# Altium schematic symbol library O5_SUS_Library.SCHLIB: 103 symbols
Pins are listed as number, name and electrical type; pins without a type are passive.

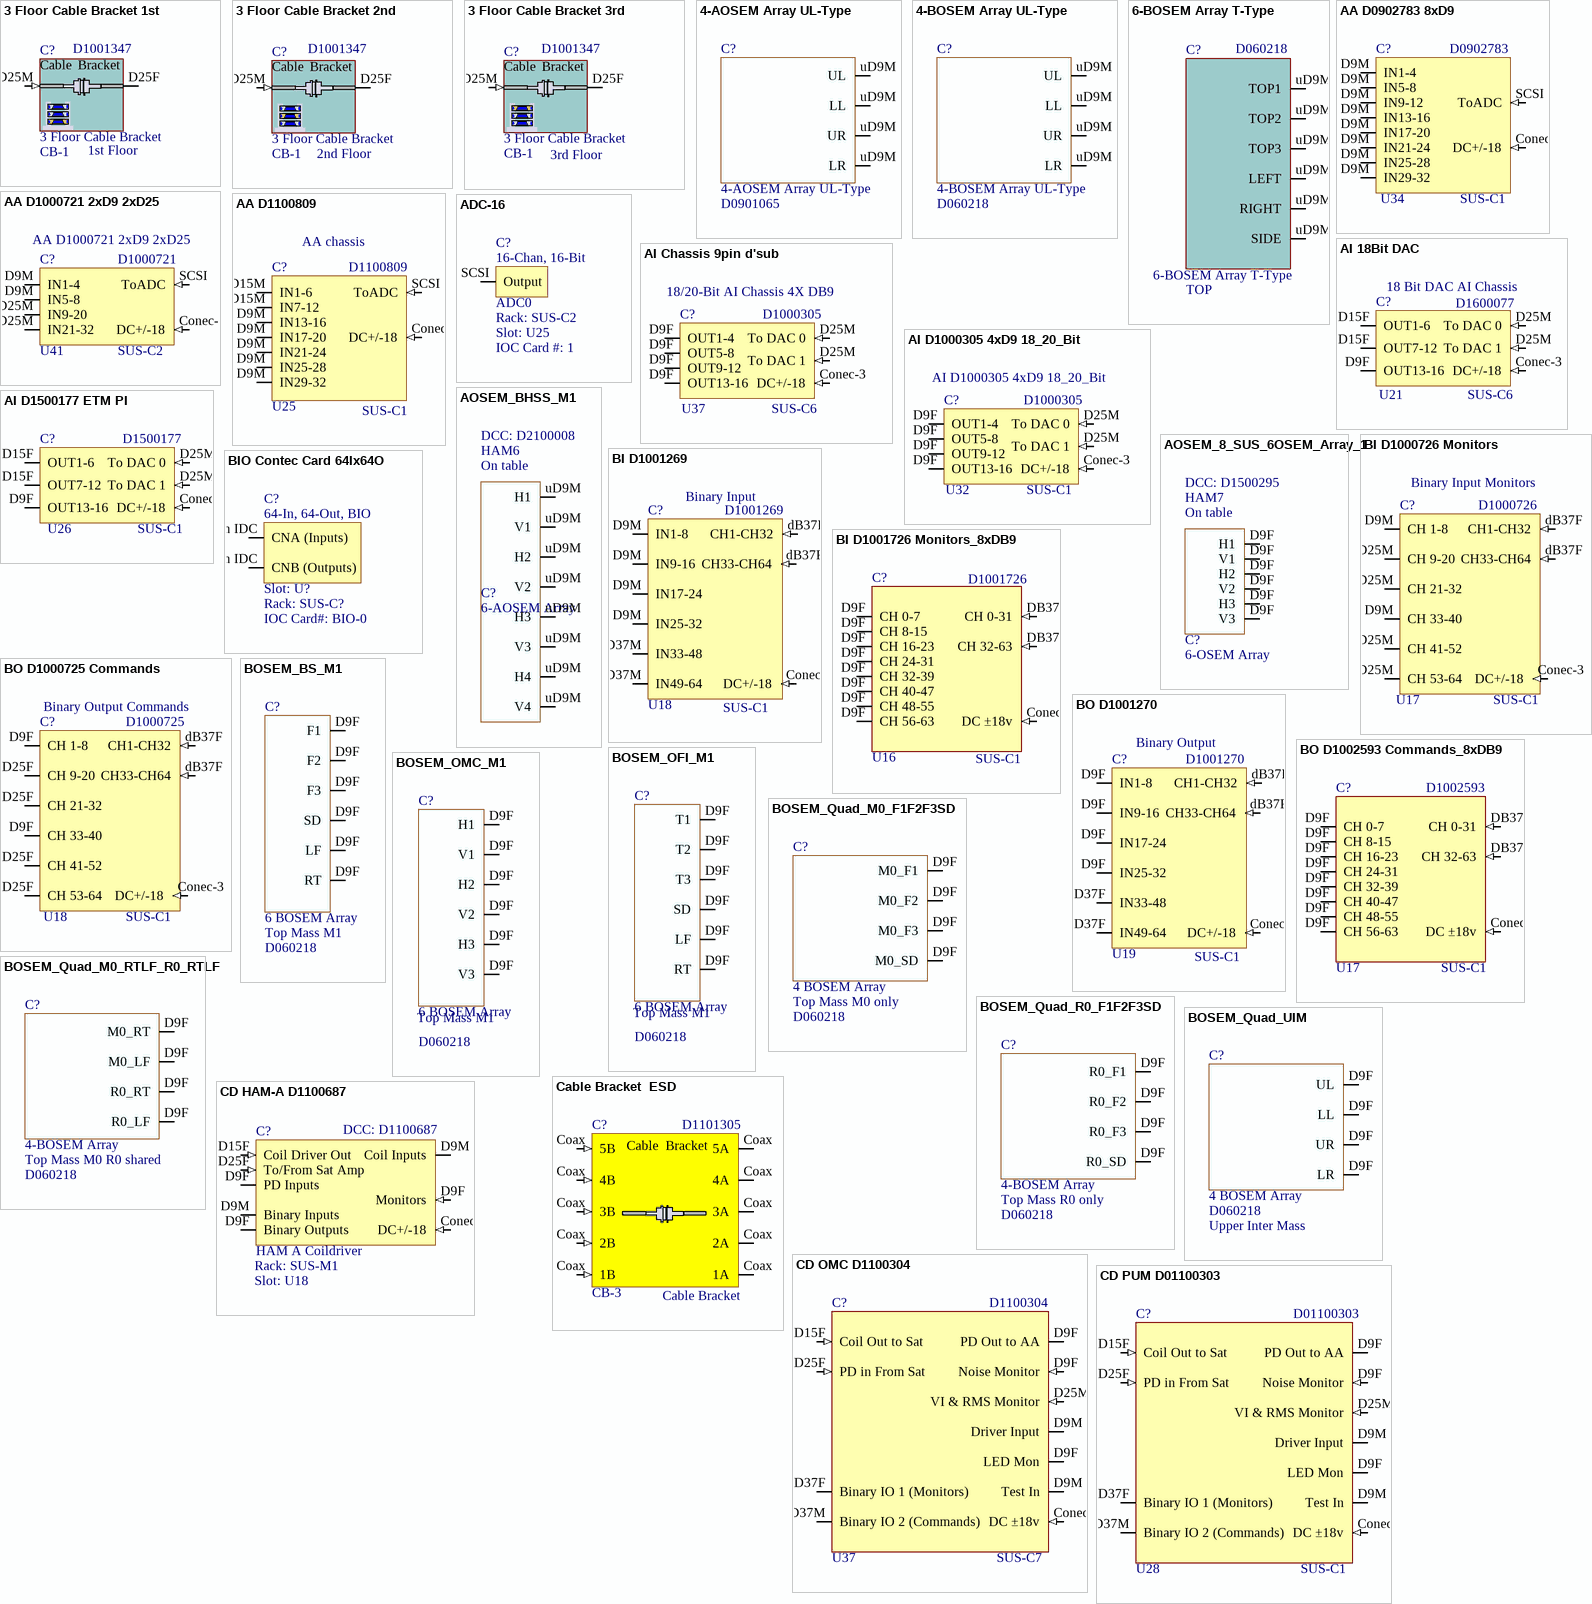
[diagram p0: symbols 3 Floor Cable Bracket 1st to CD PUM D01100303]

## 3 Floor Cable Bracket 1st
designator C?, comment 3 Floor Cable Bracket  Rack: CB-1  Slot: 1st Floor  DCC: D1001347
Cable Bracket; Serial: Sxxxxxxx; System: SUS
pins: D25F, D25M (in)

## 3 Floor Cable Bracket 2nd
designator C?, comment 3 Floor Cable Bracket  Rack: CB-1  DCC: D1001347  Slot: 2nd Floor
Cable Bracket; Serial: Sxxxxxxx; System: SUS
pins: D25F, D25M (in)

## 3 Floor Cable Bracket 3rd
designator C?, comment 3 Floor Cable Bracket  Rack: CB-1  DCC: D1001347  Slot: 3rd Floor
Cable Bracket; Serial: Sxxxxxxx; System: SUS
pins: D25F, D25M (in)

## 4-AOSEM Array UL-Type
designator C?  DCC: D0901065
Rack: R?; Slot: U?; Serial: Sxxxxxxx; System: SUS
pins: uD9M UL, uD9M LL, uD9M UR, uD9M LR

## 4-BOSEM Array UL-Type
designator C?  DCC: D060218
Rack: R?; Slot: U?; Serial: Sxxxxxxx; System: SUS
pins: uD9M UL, uD9M LL, uD9M UR, uD9M LR

## 6-BOSEM Array T-Type
designator C?  Parameter 1: TOP  DCC: D060218
Serial: Sxxxxxxx; System: SUS; Slot: U?; Rack: SUS-R?
pins: uD9M TOP1, uD9M TOP2, uD9M TOP3, uD9M LEFT, uD9M RIGHT, uD9M SIDE

## AA D0902783 8xD9
designator C?  DCC: D0902783  Rack: SUS-C1  Slot: U34  (hidden comment: AA D0902783 8xD9)
Serial: Sxxxxxxx; System: SUS
pins: Conec-3 DC+/-18 (in), D9M IN1-4, D9M IN5-8, D9M IN9-12, D9M IN13-16, D9M IN17-20, D9M IN21-24, D9M IN25-28, D9M IN29-32, SCSI ToADC (in)

## AA D1000721 2xD9 2xD25
designator C?  Slot: U41  Rack: SUS-C2  DCC: D1000721
Serial: Sxxxxxxx; System: SUS; Parameter: AA chassis
pins: Conec-3 DC+/-18 (in), D9M IN1-4, D9M IN5-8, D25M IN9-20, D25M IN21-32, SCSI ToADC (in)

## AA D1100809
designator C?, comment Slot: U25  Rack: SUS-C1  DCC: D1100809  (hidden comment: AA Chassis)
Serial: Sxxxxxxx; System: SUS
pins: Conec-3 DC+/-18 (in), D9M IN13-16, D9M IN17-20, D9M IN21-24, D9M IN25-28, D9M IN29-32, D15M IN1-6, D15M IN7-12, SCSI ToADC (in)

## ADC-16
designator C?, comment ADC0  Rack: SUS-C2  Slot: U25  IOC Card #: 1
16 Chan, 16 Bit ADC
pins: SCSI Output

## AI 18Bit DAC
designator C?, comment Rack: SUS-C6  Slot: U21  DCC: D1600077  Parameter: 18 Bit DAC AI Chassis  (hidden comment: AI chassis 18Bit)
Serial: Sxxxxxxx; System: SUS
pins: Conec-3 DC+/-18 (in), D9F OUT13-16, D15F OUT1-6, D15F OUT7-12, D25M To DAC 0 (in), D25M To DAC 1 (in)

## AI Chassis 9pin d'sub
designator C?  value 18/20-Bit AI Chassis 4X DB9  Rack: SUS-C6  Slot: U37  DCC: D1000305  (hidden comment: AI Chassis 9pin d'sub)
System: SUS; Serial: Sxxxxxxx
pins: Conec-3 DC+/-18 (in) "pin 7", D9F OUT1-4 "pin 1", D9F OUT5-8 "pin 2", D9F OUT9-12 "pin 3", D9F OUT13-16 "pin 4", D25M To DAC 0 (in) "pin 5", D25M To DAC 1 (in) "pin 6"

## AI D1000305 4xD9 18_20_Bit
designator C?  Rack: SUS-C1  Slot: U32  DCC: D1000305
System: SUS; Serial: Sxxxxxxx
pins: Conec-3 DC+/-18 (in), D9F OUT1-4, D9F OUT5-8, D9F OUT9-12, D9F OUT13-16, D25M To DAC 0 (in), D25M To DAC 1 (in)

## AI D1500177 ETM PI
designator C?, comment Rack: SUS-C1  Slot: U26  DCC: D1500177  (hidden comment: AI chassis 18Bit)
Serial: Sxxxxxxx; System: SUS; Parameter: 18 Bit DAC AI Chassis
pins: Conec-3 DC+/-18 (in), D9F OUT13-16, D15F OUT1-6, D15F OUT7-12, D25M To DAC 0 (in), D25M To DAC 1 (in)

## AOSEM_8_SUS_6OSEM_Array_1
designator C?, comment 6-OSEM Array  DCC: D1500295  Rack: HAM7  Slot: On table
OPO Suspended Platform OSEM Array
pins: D9F H1, D9F H2, D9F V1, D9F H3, D9F V2, D9F V3

## AOSEM_BHSS_M1
designator C?, comment 6-AOSEM Array  DCC: D2100008  Rack: HAM6  Slot: On table
BHSS Suspended Platform AOSEM Array
pins: uD9M H1, uD9M H2, uD9M V1, uD9M H3, uD9M V2, uD9M V3, uD9M H4, uD9M V4

## BI D1000726 Monitors
designator C?  Parameter: Binary Input Monitors  Slot: U17  Rack: SUS-C1  DCC: D1000726  (hidden comment: BI D1000726 Monitors)
Serial: Sxxxxxxx; System: SUS
pins: Conec-3 DC+/-18 (in), D9M CH 1-8, D9M CH 33-40, D25M CH 9-20, D25M CH 21-32, D25M CH 41-52, D25M CH 53-64, dB37F CH1-CH32 (in), dB37F CH33-CH64 (in)

## BI D1001269
designator C?, comment Slot: U18  Rack: SUS-C1  Parameter: Binary Input  DCC: D1001269  (hidden comment: Binary Input Interface)
Serial: Sxxxxxxx; System: SUS
pins: Conec-3 DC+/-18 (in), D9M IN1-8, D9M IN9-16, D9M IN17-24, D9M IN25-32, D37M IN33-48, D37M IN49-64, dB37F CH1-CH32 (in), dB37F CH33-CH64 (in)

## BI D1001726 Monitors_8xDB9
designator C?  Slot: U16  Rack: SUS-C1  DCC: D1001726  (hidden comment: BI D1001726 Monitors_8xDB9)
Serial: Sxxxxxxx; System: SUS
pins: Conec 3 DC ±18v (in), D9F CH 0-7, D9F CH 8-15, D9F CH 16-23, D9F CH 24-31, D9F CH 32-39, D9F CH 40-47, D9F CH 48-55, D9F CH 56-63, DB37F CH 0-31 (in), DB37F CH 32-63 (in)

## BIO Contec Card 64Ix64O
designator C?  Slot: U?  Rack: SUS-C?  IOC Card#: BIO-0  (hidden comment: BIO Contec Card 64Ix64O)
System: SUS
pins: 100Pin IDC CNA (Inputs), 100Pin IDC CNB (Outputs)

## BO D1000725 Commands
designator C?  Parameter: Binary Output Commands  Slot: U18  Rack: SUS-C1  DCC: D1000725  (hidden comment: BO D1000725 Commands)
Serial: Sxxxxxxx; System: SUS
pins: Conec-3 DC+/-18 (in), D9F CH 1-8, D9F CH 33-40, D25F CH 9-20, D25F CH 21-32, D25F CH 41-52, D25F CH 53-64, dB37F CH1-CH32 (in), dB37F CH33-CH64 (in)

## BO D1001270
designator C?, comment Slot: U19  Rack: SUS-C1  Parameter: Binary Output  DCC: D1001270  (hidden comment: Binary Output Interface)
Serial: Sxxxxxxx; System: SUS
pins: Conec-3 DC+/-18 (in), D9F IN1-8, D9F IN9-16, D9F IN17-24, D9F IN25-32, D37F IN33-48, D37F IN49-64, dB37F CH1-CH32 (in), dB37F CH33-CH64 (in)

## BO D1002593 Commands_8xDB9
designator C?  Slot: U17  Rack: SUS-C1  DCC: D1002593  (hidden comment: BO D1002593 Commands_8xDB9)
Serial: Sxxxxxxx; System: SUS
pins: Conec 3 DC ±18v (in), D9F CH 0-7, D9F CH 8-15, D9F CH 16-23, D9F CH 24-31, D9F CH 32-39, D9F CH 40-47, D9F CH 48-55, D9F CH 56-63, DB37F CH 0-31 (in), DB37F CH 32-63 (in)

## BOSEM_BS_M1
designator C?, comment 6 BOSEM Array  Parameter: Top Mass M1  DCC: D060218
BOSEM; Serial: Sxxxxxxx; System: SUS; Rack: R?; Slot: U?
pins: D9F F1, D9F F2, D9F F3, D9F SD, D9F LF, D9F RT

## BOSEM_OFI_M1
designator C?, comment 6 BOSEM Array  Parameter: Top Mass M1  DCC: D060218
BOSEM; Serial: Sxxxxxxx; System: SUS; Rack: R?; Slot: U?
pins: D9F T1, D9F T2, D9F T3, D9F SD, D9F LF, D9F RT

## BOSEM_OMC_M1
designator C?, comment 6 BOSEM Array  Parameter: Top Mass M1  DCC: D060218
BOSEM; Serial: Sxxxxxxx; System: SUS; Rack: R?; Slot: U?
pins: D9F H1, D9F V1, D9F H2, D9F V2, D9F H3, D9F V3

## BOSEM_Quad_M0_F1F2F3SD
designator C?, comment 4 BOSEM Array  Parameter: Top Mass M0 only  DCC: D060218
BOSEM; Serial: Sxxxxxxx; System: SUS; Rack: R?; Slot: U?
pins: D9F M0_F1, D9F M0_F2, D9F M0_F3, D9F M0_SD

## BOSEM_Quad_M0_RTLF_R0_RTLF
designator C?, comment 4-BOSEM Array  Parameter: Top Mass M0 R0 shared  DCC: D060218
BOSEM; Rack: R?; Slot: U?; Serial: Sxxxxxxx; System: SUS
pins: D9F M0_RT, D9F M0_LF, D9F R0_RT, D9F R0_LF

## BOSEM_Quad_R0_F1F2F3SD
designator C?, comment 4-BOSEM Array  Parameter: Top Mass R0 only  DCC: D060218
BOSEM; System: SUS; Slot: U?; Serial: Sxxxxxxx; Rack: R?
pins: D9F R0_F2, D9F R0_F1, D9F R0_SD, D9F R0_F3

## BOSEM_Quad_UIM
designator C?, comment 4 BOSEM Array  DCC: D060218  Parameter: Upper Inter Mass
BOSEM; Rack: R?; Serial: Sxxxxxxx; Slot: U?; System: SUS
pins: D9F UL, D9F LL, D9F UR, D9F LR

## Cable Bracket  ESD
designator C?, comment Slot: CB-3  DCC: D1101305  (hidden comment: Cable Bracket)
Rack: SUS-R?; Serial: Sxxxxxxx; System: SUS
pins: Coax 5B (in), Coax 5A, Coax 4A, Coax 3A, Coax 2A, Coax 1A, Coax 4B (in), Coax 3B (in), Coax 2B (in), Coax 1B (in)

## CD HAM-A D1100687
designator C?, comment HAM A Coildriver  DCC: D1100687  Rack: SUS-M1  Slot: U18
Serial: Sxxxxxxx; System: ISC
pins: Conec-3 DC+/-18 (in), D9F PD Inputs, D9F Monitors (in), D9F Binary Outputs, D9M Coil Inputs, D9M Binary Inputs, D15F Coil Driver Out (in), D25F To/From Sat Amp (in)

## CD OMC D1100304
designator C?, comment Slot: U37  Rack: SUS-C7  DCC: D1100304  (hidden comment: CD OMC TCD D1100304)
System: SUS; Serial: Sxxxxxxx
pins: Conec 3 DC ±18v (in), D9F PD Out to AA, D9F LED Mon, D9F Noise Monitor (in), D9M Test In, D9M Driver Input, D15F Coil Out to Sat (in), D25F PD in From Sat (in), D25M VI & RMS Monitor (in), D37F Binary IO 1 (Monitors), D37M Binary IO 2 (Commands)

## CD PUM D01100303
designator C?  Slot: U28  Rack: SUS-C1  DCC: D01100303  (hidden comment: CD PUM D01100303)
System: SUS; Serial: Sxxxxxxx
pins: Conec 3 DC ±18v (in), D9F PD Out to AA, D9F LED Mon, D9F Noise Monitor (in), D9M Test In, D9M Driver Input, D15F Coil Out to Sat (in), D25F PD in From Sat (in), D25M VI & RMS Monitor (in), D37F Binary IO 1 (Monitors), D37M Binary IO 2 (Commands)

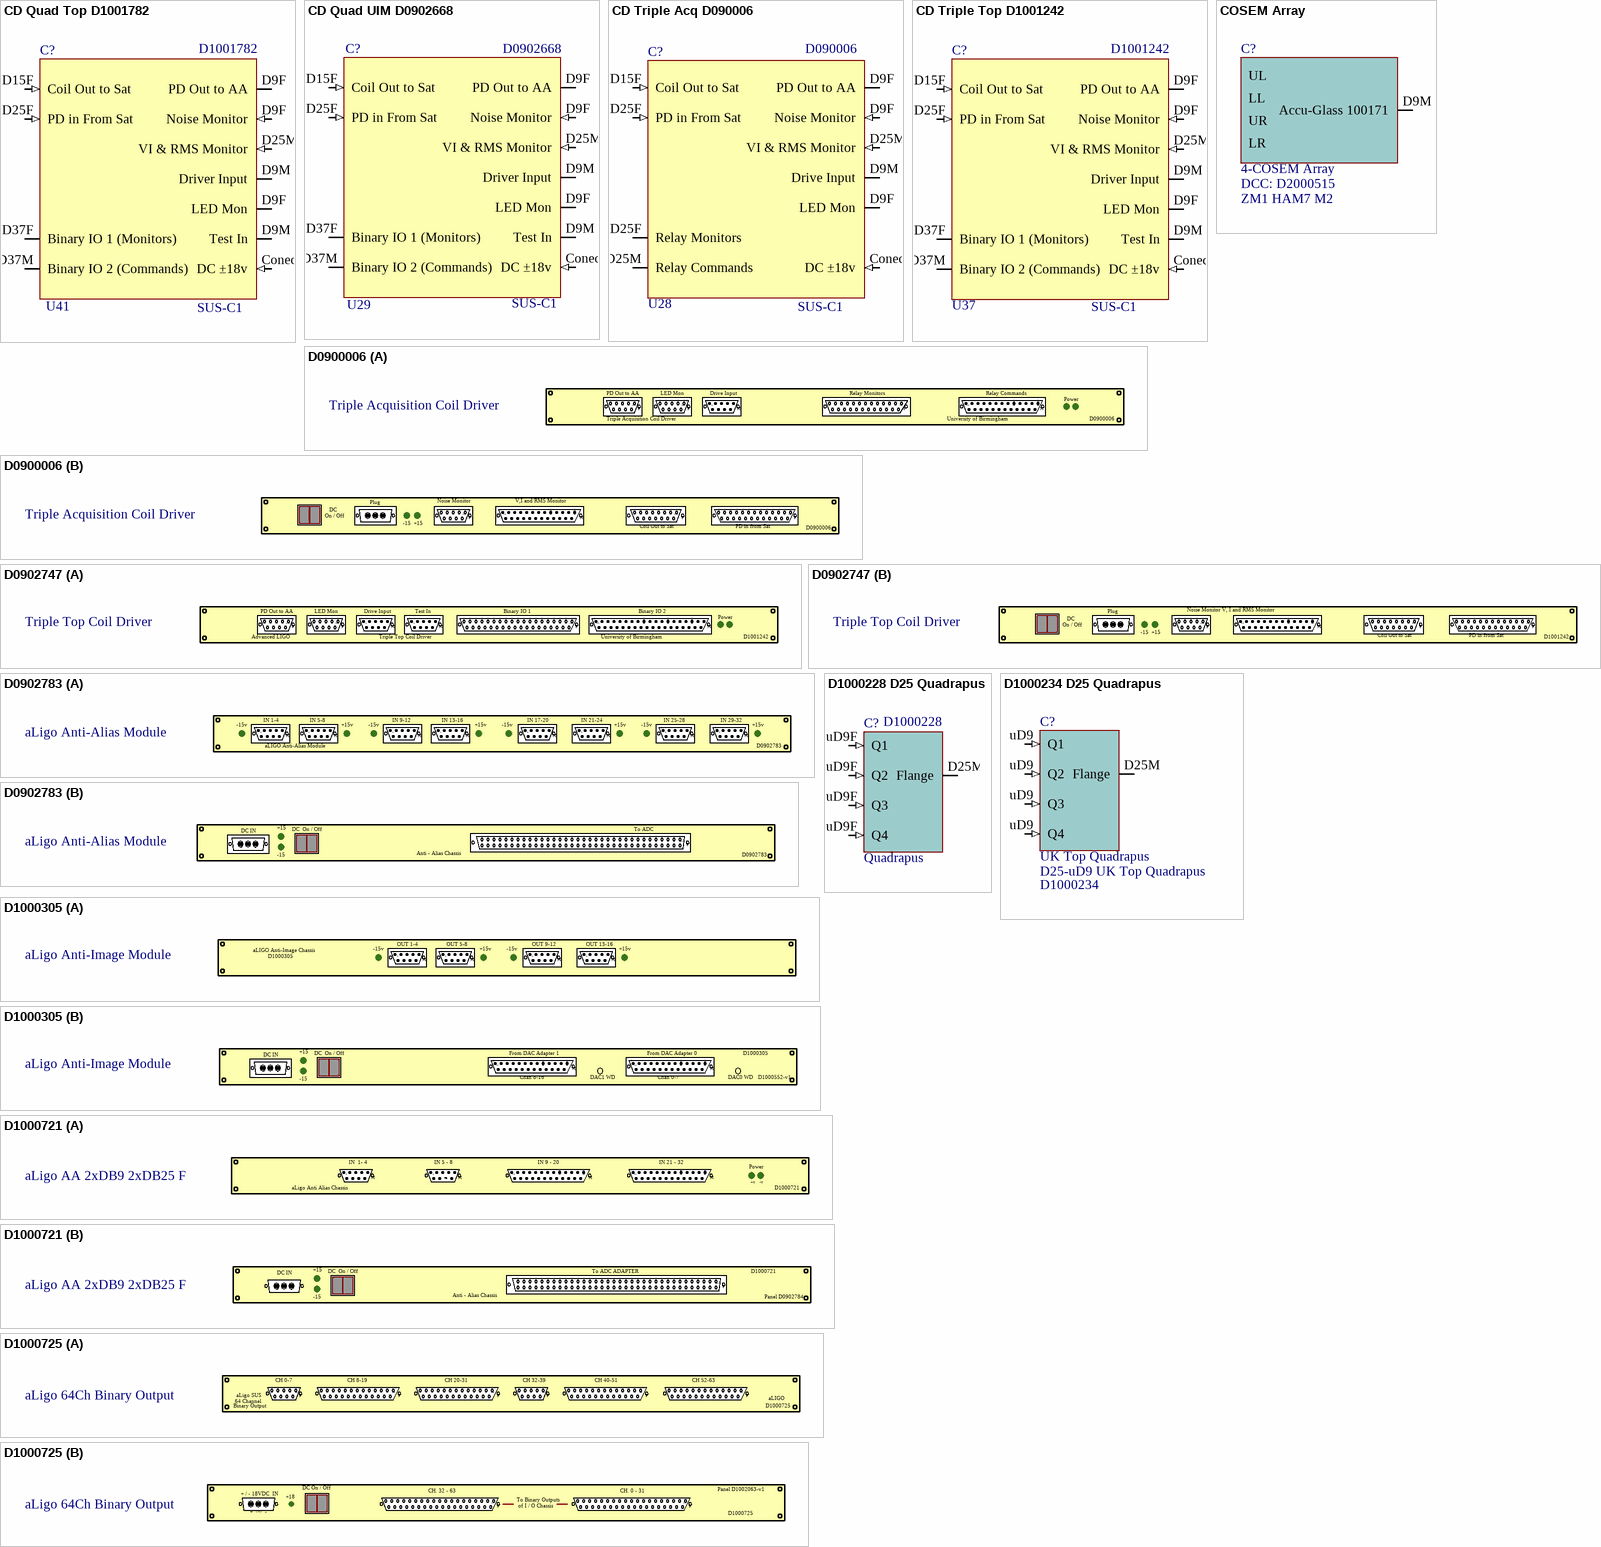
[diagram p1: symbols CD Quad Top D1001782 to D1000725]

## CD Quad Top D1001782
designator C?  Rack: SUS-C1  Slot: U41  DCC: D1001782  (hidden comment: CD Quad Top D1001782)
Serial: Sxxxxxxx; System: SUS; Parameter: Quad Top Coil Driver
pins: Conec 3 DC ±18v (in), D9F PD Out to AA, D9F LED Mon, D9F Noise Monitor (in), D9M Test In, D9M Driver Input, D15F Coil Out to Sat (in), D25F PD in From Sat (in), D25M VI & RMS Monitor (in), D37F Binary IO 1 (Monitors), D37M Binary IO 2 (Commands)

## CD Quad UIM D0902668
designator C?  Slot: U29  Rack: SUS-C1  DCC: D0902668  (hidden comment: CD Quad UIM D0902668)
System: SUS; Serial: Sxxxxxxx
pins: Conec 3 DC ±18v (in), D9F PD Out to AA, D9F LED Mon, D9F Noise Monitor (in), D9M Test In, D9M Driver Input, D15F Coil Out to Sat (in), D25F PD in From Sat (in), D25M VI & RMS Monitor (in), D37F Binary IO 1 (Monitors), D37M Binary IO 2 (Commands)

## CD Triple Acq D090006
designator C?  Slot: U28  Rack: SUS-C1  DCC: D090006  (hidden comment: CD Triple Acq D090006)
System: SUS; Serial: Sxxxxxxx
pins: Conec 3 DC ±18v (in), D9F PD Out to AA, D9F LED Mon, D9F Noise Monitor (in), D9M Drive Input, D15F Coil Out to Sat (in), D25F Relay Monitors, D25F PD in From Sat (in), D25M Relay Commands, D25M VI & RMS Monitor (in)

## CD Triple Top D1001242
designator C?  Slot: U37  Rack: SUS-C1  DCC: D1001242  (hidden comment: CD Triple Top D1001242)
System: SUS; Serial: Sxxxxxxx
pins: Conec 3 DC ±18v (in), D9F PD Out to AA, D9F LED Mon, D9F Noise Monitor (in), D9M Test In, D9M Driver Input, D15F Coil Out to Sat (in), D25F PD in From Sat (in), D25M VI & RMS Monitor (in), D37F Binary IO 1 (Monitors), D37M Binary IO 2 (Commands)

## COSEM Array
designator C?, comment value 4-COSEM Array  Rack: ZM1 HAM7 M2  DCC: D2000515  (hidden comment: Cable)
Serial: Sxxxxxxx; Slot: U?; System: SUS
pins: D9M Accu-Glass 100171

## D0900006
designator Chassis25_A?, comment Triple Acquisition Coil Driver

## D0902747
designator Chassis41_A?, comment Triple Top Coil Driver

## D0902783
designator Chassis40_A?, comment aLigo Anti-Alias Module

## D1000228 D25 Quadrapus
designator C?, comment Quadrapus  DCC: D1000228
D1000228 D25 Quadrapus; Slot: U?; Rack: R?; Serial: Sxxxxxxx; System: SUS
pins: D25M Flange, uD9F Q1 (in), uD9F Q2 (in), uD9F Q3 (in), uD9F Q4 (in)

## D1000234 D25 Quadrapus
designator C?, comment UK Top Quadrapus  Parameter: D25-uD9 UK Top Quadrapus  DCC: D1000234
D1000234 D25 Quadrapus; Slot: U?; Rack: R?; Serial: Sxxxxxxx; System: SUS
pins: D25M Flange, uD9 Q1 (in), uD9 Q2 (in), uD9 Q3 (in), uD9 Q4 (in)

## D1000305
designator Chassis39_A?, comment aLigo Anti-Image Module

## D1000721
designator Chassis38_A?, comment aLigo AA 2xDB9 2xDB25 F

## D1000725
designator Chassis37_A?, comment aLigo 64Ch Binary Output

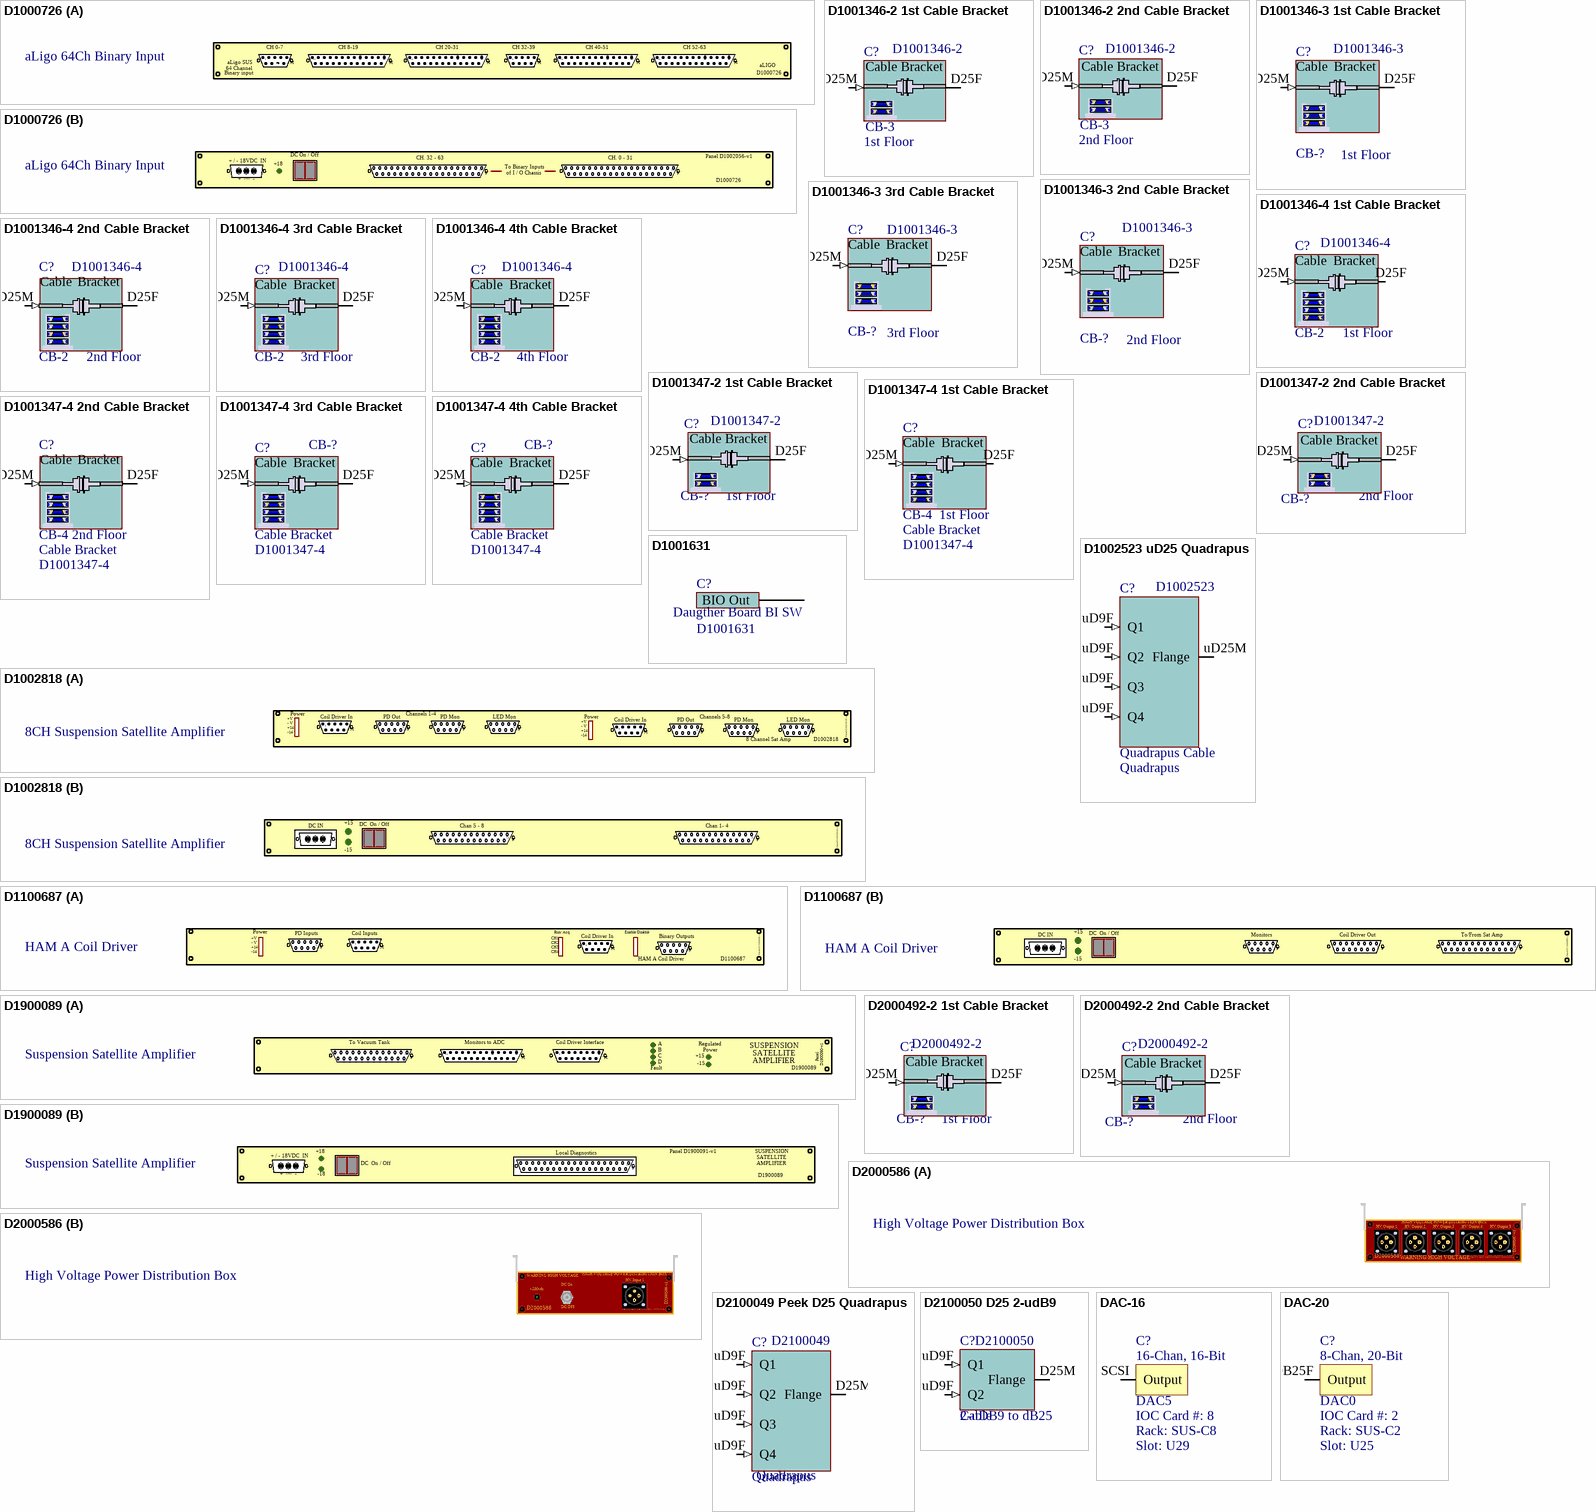
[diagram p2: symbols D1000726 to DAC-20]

## D1000726
designator Chassis36_A?, comment aLigo 64Ch Binary Input

## D1001346-2 1st Cable Bracket
designator C?, comment Rack: CB-3  Slot: 1st Floor  DCC: D1001346-2  (hidden comment: Cable Bracket)
D1001346-2 1/2 Cable Bracket for HAM Tables; Serial: Sxxxxxxx; System: SUS
pins: D25F, D25M (in)

## D1001346-2 2nd Cable Bracket
designator C?, comment Rack: CB-3  Slot: 2nd Floor  DCC: D1001346-2  (hidden comment: Cable Bracket)
D1001346-2 2/2 Cable Bracket for HAM Tables; Serial: Sxxxxxxx; System: SUS
pins: D25F, D25M (in)

## D1001346-3 1st Cable Bracket
designator C?  Rack: CB-?  Slot: 1st Floor  DCC: D1001346-3  (hidden comment: D1001346-3 1st Cable Bracket)
D1001346-3 1st Cable Bracket  for HAM Tables; Serial: Sxxxxxxx; System: SUS
pins: D25F, D25M (in)

## D1001346-3 2nd Cable Bracket
designator C?  Rack: CB-?  DCC: D1001346-3  Slot: 2nd Floor  (hidden comment: D1001346-3 2nd Cable Bracket)
D1001346-3 2nd Cable Bracket  for HAM Tables; Serial: Sxxxxxxx; System: SUS
pins: D25F, D25M (in)

## D1001346-3 3rd Cable Bracket
designator C?  Rack: CB-?  DCC: D1001346-3  Slot: 3rd Floor  (hidden comment: D1001346-3 3rd Cable Bracket)
D1001346-3 3rd Cable Bracket for HAM Tables; Serial: Sxxxxxxx; System: SUS
pins: D25F, D25M (in)

## D1001346-4 1st Cable Bracket
designator C?  Rack: CB-2  Slot: 1st Floor  DCC: D1001346-4  (hidden comment: D1001346-4 1st Cable Bracket)
Serial: Sxxxxxxx; System: SUS
pins: D25F, D25M (in)

## D1001346-4 2nd Cable Bracket
designator C?  Rack: CB-2  Slot: 2nd Floor  DCC: D1001346-4  (hidden comment: D1001346-4 2nd Cable Bracket)
Serial: Sxxxxxxx; System: SUS
pins: D25F, D25M (in)

## D1001346-4 3rd Cable Bracket
designator C?  Rack: CB-2  Slot: 3rd Floor  DCC: D1001346-4  (hidden comment: D1001346-4 3rd Cable Bracket)
Serial: Sxxxxxxx; System: SUS
pins: D25F, D25M (in)

## D1001346-4 4th Cable Bracket
designator C?  Rack: CB-2  Slot: 4th Floor  DCC: D1001346-4  (hidden comment: D1001346-4 4th Cable Bracket)
Serial: Sxxxxxxx; System: SUS
pins: D25F, D25M (in)

## D1001347-2 1st Cable Bracket
designator C?, comment Rack: CB-?  Slot: 1st Floor  DCC: D1001347-2  (hidden comment: Cable Bracket)
D1001347-2 1/2 Cable Bracket for BSC Tables; Serial: Sxxxxxxx; System: SUS
pins: D25F, D25M (in)

## D1001347-2 2nd Cable Bracket
designator C?, comment Rack: CB-?  Slot: 2nd Floor  DCC: D1001347-2  (hidden comment: Cable Bracket)
D1001347-2 2/2 Cable Bracket for BSC Tables; Serial: Sxxxxxxx; System: SUS
pins: D25F, D25M (in)

## D1001347-4 1st Cable Bracket
designator C?  value Cable Bracket  Slot: CB-4  1st Floor  DCC: D1001347-4  (hidden comment: D1001347-4 1st Cable Bracket)
Rack: SUS-R?; Serial: Sxxxxxxx; System: SUS
pins: D25F, D25M (in)

## D1001347-4 2nd Cable Bracket
designator C?  value Cable Bracket  Slot: CB-4 2nd Floor  DCC: D1001347-4  (hidden comment: D1001347-4 2nd Cable Bracket)
Rack: SUS-R?; Serial: Sxxxxxxx; System: SUS
pins: D25F, D25M (in)

## D1001347-4 3rd Cable Bracket
designator C?  value Cable Bracket  Slot: CB-?  DCC: D1001347-4  (hidden comment: D1001347-4 3rd Cable Bracket)
Rack: SUS-R?; Serial: Sxxxxxxx; System: SUS
pins: D25F, D25M (in)

## D1001347-4 4th Cable Bracket
designator C?  value Cable Bracket  Slot: CB-?  DCC: D1001347-4  (hidden comment: D1001347-4 4th Cable Bracket)
Rack: SUS-R?; Serial: Sxxxxxxx; System: SUS
pins: D25F, D25M (in)

## D1001631
designator C?, comment Daugther Board BI SW  DCC: D1001631
Rack: SUS-R?; Serial: Sxxxxxxx; Slot: U?; System: SUS
pins: D37M BIO Out

## D1002523 uD25 Quadrapus
designator C?, comment Quadrapus Cable  value Quadrapus  DCC: D1002523
Rack: SUS-R?; Serial: Sxxxxxxx; Slot: U?; System: SUS
pins: uD9F Q1 (in), uD9F Q2 (in), uD9F Q3 (in), uD9F Q4 (in), uD25M Flange

## D1002818
designator Chassis42_2A?, comment 8CH Suspension Satellite Amplifier
8CH Sat Amp

## D1100687
designator Chassis41_2A?, comment HAM A Coil Driver

## D1900089
designator Chassis?, comment Suspension Satellite Amplifier

## D2000492-2 1st Cable Bracket
designator C?, comment Rack: CB-?  Slot: 1st Floor  DCC: D2000492-2  (hidden comment: Cable Bracket)
D2000492-2 1/2 Cable Bracket for BSC Tables; Serial: Sxxxxxxx; System: SUS
pins: D25F, D25M (in)

## D2000492-2 2nd Cable Bracket
designator C?, comment Rack: CB-?  Slot: 2nd Floor  DCC: D2000492-2  (hidden comment: Cable Bracket)
D2000492-2 2/2 Cable Bracket for BSC Tables; Serial: Sxxxxxxx; System: SUS
pins: D25F, D25M (in)

## D2000586
designator C?, comment High Voltage Power Distribution Box

## D2100049 Peek D25 Quadrapus
designator C?, comment Quadrapus  DCC: D2100049
D2100049 Peek D25 Quadrapus; Slot: U?; Rack: R?; Serial: Sxxxxxxx; System: SUS
pins: D25M Flange, uD9F Q1 (in), uD9F Q2 (in), uD9F Q3 (in), uD9F Q4 (in)

## D2100050 D25 2-udB9
designator C?, comment Cable  value 2-uDB9 to dB25  DCC: D2100050
Rack: SUS-R?; Serial: Sxxxxxxx; Slot: U?; System: SUS
pins: D25M Flange, uD9F Q1 (in), uD9F Q2 (in)

## DAC-16
designator C?, comment DAC5  IOC Card #: 8  Rack: SUS-C8  Slot: U29
16 Chan, 16 Bit DAC
pins: SCSI Output

## DAC-20
designator C?, comment DAC0  IOC Card #: 2  Rack: SUS-C2  Slot: U25
8 Chan, 20 Bit DAC
pins: DB25F Output

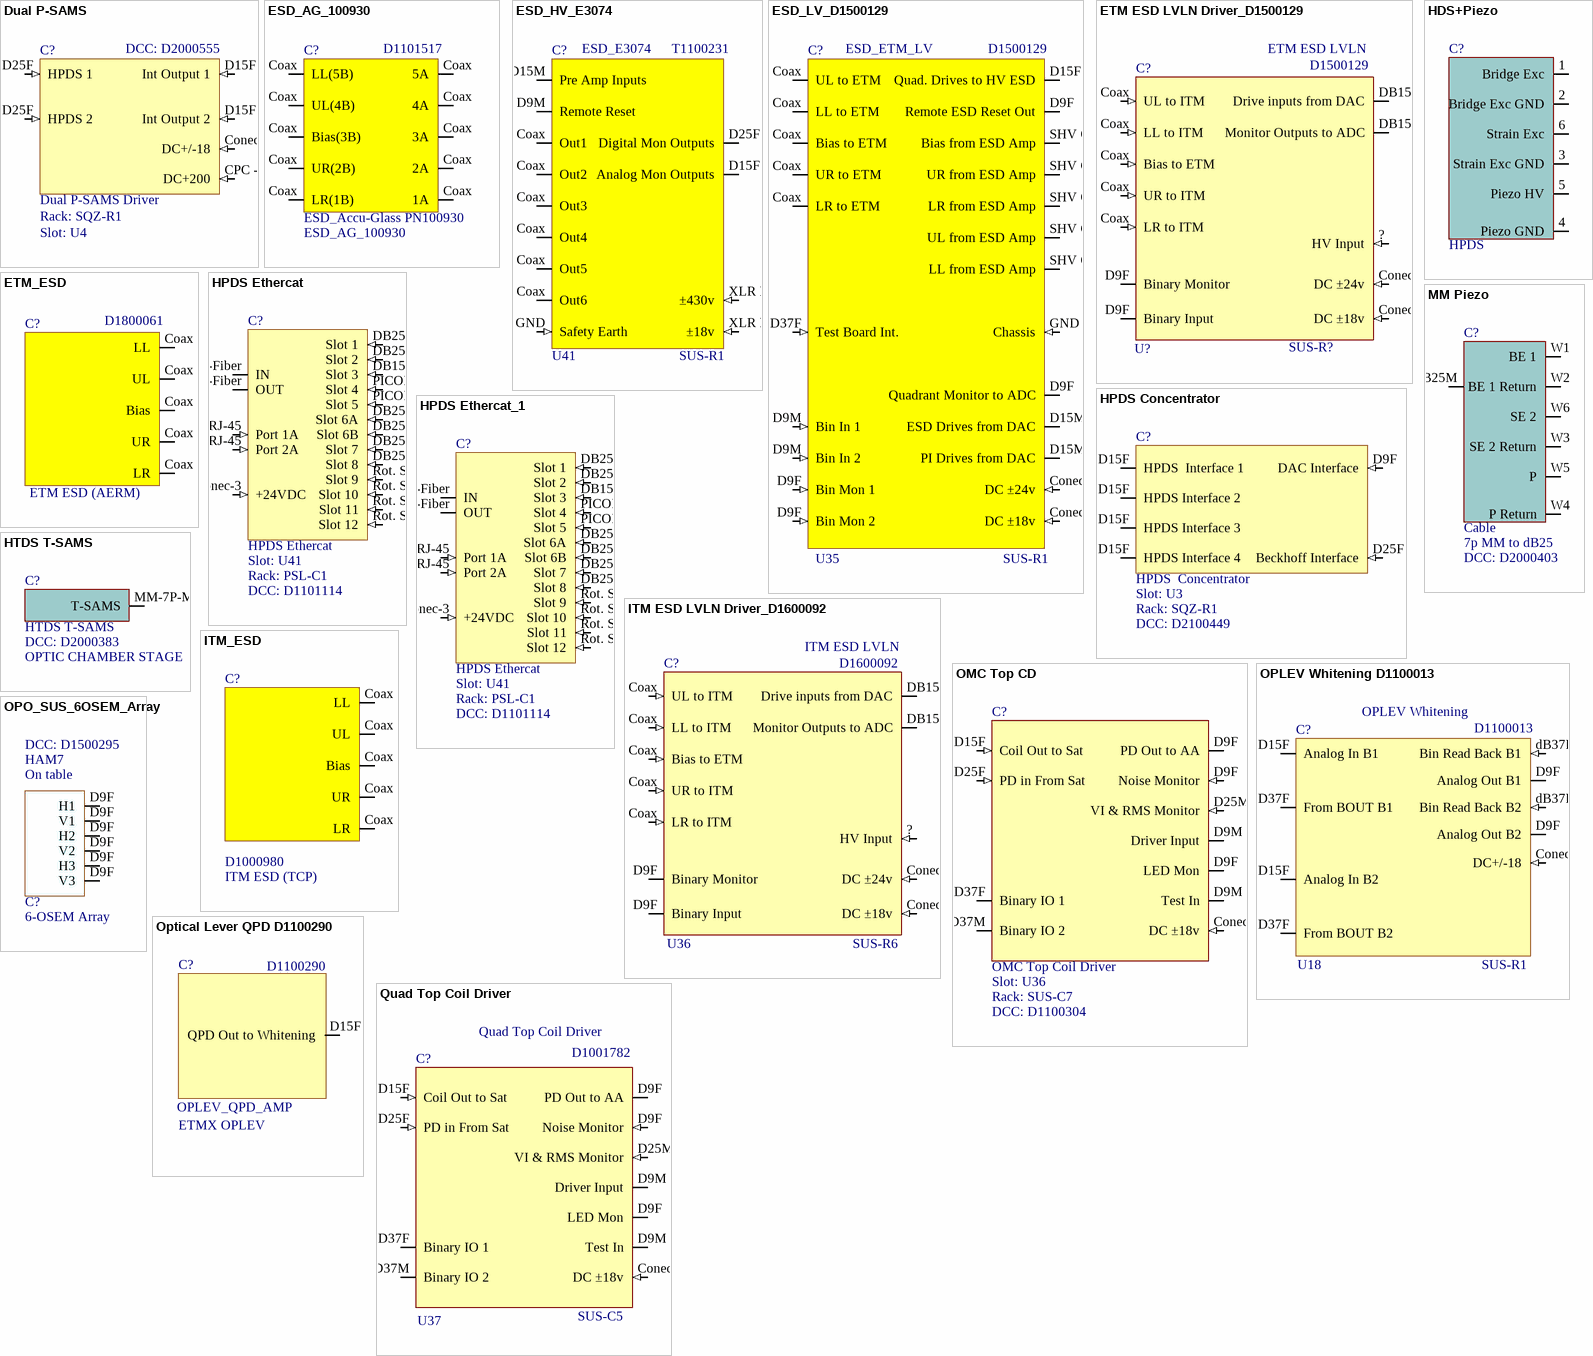
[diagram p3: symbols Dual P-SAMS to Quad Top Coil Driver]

## Dual P-SAMS
designator C?, comment Dual P-SAMS Driver  Slot: U4  Rack: SQZ-R1  DCC: D2000555
Strain Gauge and PZT Driver; Serial: Sxxxxxxx; System: SUS
pins: Conec-3 DC+/-18 (in), CPC - 3 DC+200 (in), D15F Int Output 1 (in), D15F Int Output 2 (in), D25F HPDS 1 (in), D25F HPDS 2 (in)

## ESD_AG_100930
designator C?, comment ESD_Accu-Glass PN100930  Parameter: ESD_AG_100930  DCC: D1101517
ESD_Accu-Glass; Rack: R?; Serial: Sxxxxxxxx; Slot: U?; System: SUS
pins: Coax UL(4B), Coax 5A, Coax Bias(3B), Coax LR(1B), Coax UR(2B), Coax LL(5B), Coax 4A, Coax 3A, Coax 2A, Coax 1A

## ESD_HV_E3074
designator C?, comment Rack: SUS-R1  Slot: U41  DCC: T1100231  (hidden comment: ESD_E3074)
Serial: Sxxxxxxxx; System: SUS
pins: Coax Out2, Coax Out3, Coax Out5, Coax Out4, Coax Out1, Coax Out6, D9M Remote Reset, D15F Analog Mon Outputs, D15M Pre Amp Inputs, D25F Digital Mon Outputs, GND Safety Earth (in), XLR Plug 3p ±430v (in), XLR Plug 3p ±18v (in)

## ESD_LV_D1500129
designator C?, comment Rack: SUS-R1  Slot: U35  Parameter: ESD_ETM_LV  DCC: D1500129  (hidden comment: ESD_ETM_LV_Driver)
Serial: Sxxxxxxxx; System: SUS
pins: Coax UL to ETM, Coax LL to ETM, Coax Bias to ETM, Coax UR to ETM, Coax LR to ETM, Conec 3 DC ±24v (in), Conec 3 DC ±18v (in), D9F Bin Mon 1 (in), D9F Bin Mon 2 (in), D9F Remote ESD Reset Out, D9F Quadrant Monitor to ADC, D9M Bin In 1 (in), D9M Bin In 2 (in), D15F Quad. Drives to HV ESD, D15M PI Drives from DAC, D15M ESD Drives from DAC, D37F Test Board Int. (in), GND Chassis (in), SHV Coax Bias from ESD Amp, SHV Coax UR from ESD Amp, SHV Coax LR from ESD Amp, SHV Coax UL from ESD Amp, SHV Coax LL from ESD Amp

## ETM ESD LVLN Driver_D1500129
designator C?, comment ETM ESD LVLN  Slot: U?  Rack: SUS-R?  DCC: D1500129
ETM ESD Low Voltage Low Noise Driver; System: SUS; Serial: Sxxxxxxx
pins: ? HV Input (in), Coax UL to ITM (in), Coax LL to ITM (in), Coax Bias to ETM (in), Coax UR to ITM (in), Coax LR to ITM (in), Conec 3 DC ±18v (in), Conec 3 DC ±24v (in), D9F Binary Monitor, D9F Binary Input, DB15 Drive inputs from DAC, DB15 Monitor Outputs to ADC

## ETM_ESD
designator C?, comment DCC: D1800061  Parameter: ETM ESD (AERM)  (hidden comment: ETM)
System: SUS; Rack: R?; Slot: U?; Serial: Sxxxxxxxx
pins: Coax UL, Coax LL, Coax Bias, Coax LR, Coax UR

## HDS+Piezo
designator C?, comment HPDS
HAM Double Suspension with Piezo Driver
pins: 1 Bridge Exc, 2 Bridge Exc GND, 3 Strain Exc GND, 4 Piezo GND, 5 Piezo HV, 6 Strain Exc

## HPDS Concentrator
designator C?, comment HPDS  Concentrator  Slot: U3  Rack: SQZ-R1  DCC: D2100449
Serial: S?; System: SUS
pins: D9F DAC Interface (in), D15F HPDS  Interface 1, D15F HPDS Interface 2, D15F HPDS Interface 3, D15F HPDS Interface 4, D25F Beckhoff Interface (in)

## HPDS Ethercat
designator C?  Slot: U41  Rack: PSL-C1  DCC: D1101114
PSL - C1; System: MISC; Serial: Sxxxxxxx
pins: Conec-3 +24VDC (in), DB15M Slot 3 (in), DB25F Slot 1 (in), DB25F Slot 2 (in), DB25F Slot 6A (in), DB25F Slot 6B (in), DB25M Slot 8 (in), DB25M Slot 7 (in), LC-Fiber IN, LC-Fiber OUT, PICOMOTOR Slot 4 (in), PICOMOTOR Slot 5 (in), RJ-45 Port 1A (in), RJ-45 Port 2A (in), Rot. Stage Slot 9 (in), Rot. Stage Slot 10 (in), Rot. Stage Slot 11 (in), Rot. Stage Slot 12 (in)

## HPDS Ethercat_1
designator C?, comment HPDS Ethercat  Slot: U41  Rack: PSL-C1  DCC: D1101114
PSL - C1; System: MISC; Serial: Sxxxxxxx
pins: Conec-3 +24VDC (in), DB15M Slot 3 (in), DB25F Slot 1 (in), DB25F Slot 2 (in), DB25F Slot 6A (in), DB25F Slot 6B (in), DB25M Slot 8 (in), DB25M Slot 7 (in), LC-Fiber IN, LC-Fiber OUT, PICOMOTOR Slot 4 (in), PICOMOTOR Slot 5 (in), RJ-45 Port 1A (in), RJ-45 Port 2A (in), Rot. Stage Slot 9 (in), Rot. Stage Slot 10 (in), Rot. Stage Slot 11 (in), Rot. Stage Slot 12 (in)

## HTDS T-SAMS
designator C?  DCC: D2000383  Location: OPTIC CHAMBER STAGE
Heater and two thermistors; Rack: SUS-R?; Serial: Sxxxxxxx; Slot: U?; System: SUS
pins: MM-7P-M T-SAMS

## ITM ESD LVLN Driver_D1600092
designator C?, comment ITM ESD LVLN  Slot: U36  Rack: SUS-R6  DCC: D1600092
ITM ESD Low Voltage Low Noise Driver; System: SUS; Serial: Sxxxxxxx
pins: ? HV Input (in), Coax UL to ITM (in), Coax LL to ITM (in), Coax Bias to ETM (in), Coax UR to ITM (in), Coax LR to ITM (in), Conec 3 DC ±18v (in), Conec 3 DC ±24v (in), D9F Binary Monitor, D9F Binary Input, DB15 Drive inputs from DAC, DB15 Monitor Outputs to ADC

## ITM_ESD
designator C?, comment DCC: D1000980  Parameter: ITM ESD (TCP)  (hidden comment: ITM)
System: SUS; Rack: R?; Slot: U?; Serial: Sxxxxxxxx
pins: Coax UL, Coax LL, Coax Bias, Coax LR, Coax UR

## MM Piezo
designator C?, comment Cable  value 7p MM to dB25  DCC: D2000403
Piezo or Thermal; Rack: SUS-R?; Serial: Sxxxxxxx; Slot?: U?; System: SUS
pins: DB25M 7, W1 BE 1, W2 BE 1 Return, W3 SE 2 Return, W4 P Return, W5 P, W6 SE 2

## OMC Top CD
designator C?, comment OMC Top Coil Driver  Slot: U36  Rack: SUS-C7  DCC: D1100304
System: SUS; Serial: Sxxxxxxx
pins: Conec 3 DC ±18v (in), D9F PD Out to AA, D9F LED Mon, D9F Noise Monitor (in), D9M Test In, D9M Driver Input, D15F Coil Out to Sat (in), D25F PD in From Sat (in), D25M VI & RMS Monitor (in), D37F Binary IO 1, D37M Binary IO 2

## OPLEV Whitening D1100013
designator C?, comment Rack: SUS-R1  DCC: D1100013  Parameter: OPLEV Whitening  Slot: U18  (hidden comment: 8CH OPLEV Whitening)
System: SUS; Serial: Sxxxxxxx
pins: Conec-3 DC+/-18 (in), D9F Analog Out B1, D9F Analog Out B2, D15F Analog In B1, D15F Analog In B2, D37F From BOUT B1, D37F From BOUT B2, dB37F Bin Read Back B1 (in), dB37F Bin Read Back B2 (in)

## OPO_SUS_6OSEM_Array
designator C?, comment 6-OSEM Array  DCC: D1500295  Rack: HAM7  Slot: On table
OPO Suspended Platform OSEM Array
pins: D9F H1, D9F H2, D9F V1, D9F H3, D9F V2, D9F V3

## Optical Lever QPD D1100290
designator C?, comment Rack: ETMX OPLEV  DCC: D1100290  Parameter: OPLEV_QPD_AMP  (hidden comment: Optical Level QPD Amp)
Serial: Sxxxxxxxx
pins: D15F QPD Out to Whitening

## Quad Top Coil Driver
designator C?  Rack: SUS-C5  Slot: U37  DCC: D1001782  (hidden comment: Quad Top Coil Driver)
Serial: Sxxxxxxx; System: SUS
pins: Conec 3 DC ±18v (in), D9F PD Out to AA, D9F LED Mon, D9F Noise Monitor (in), D9M Test In, D9M Driver Input, D15F Coil Out to Sat (in), D25F PD in From Sat (in), D25M VI & RMS Monitor (in), D37F Binary IO 1, D37M Binary IO 2

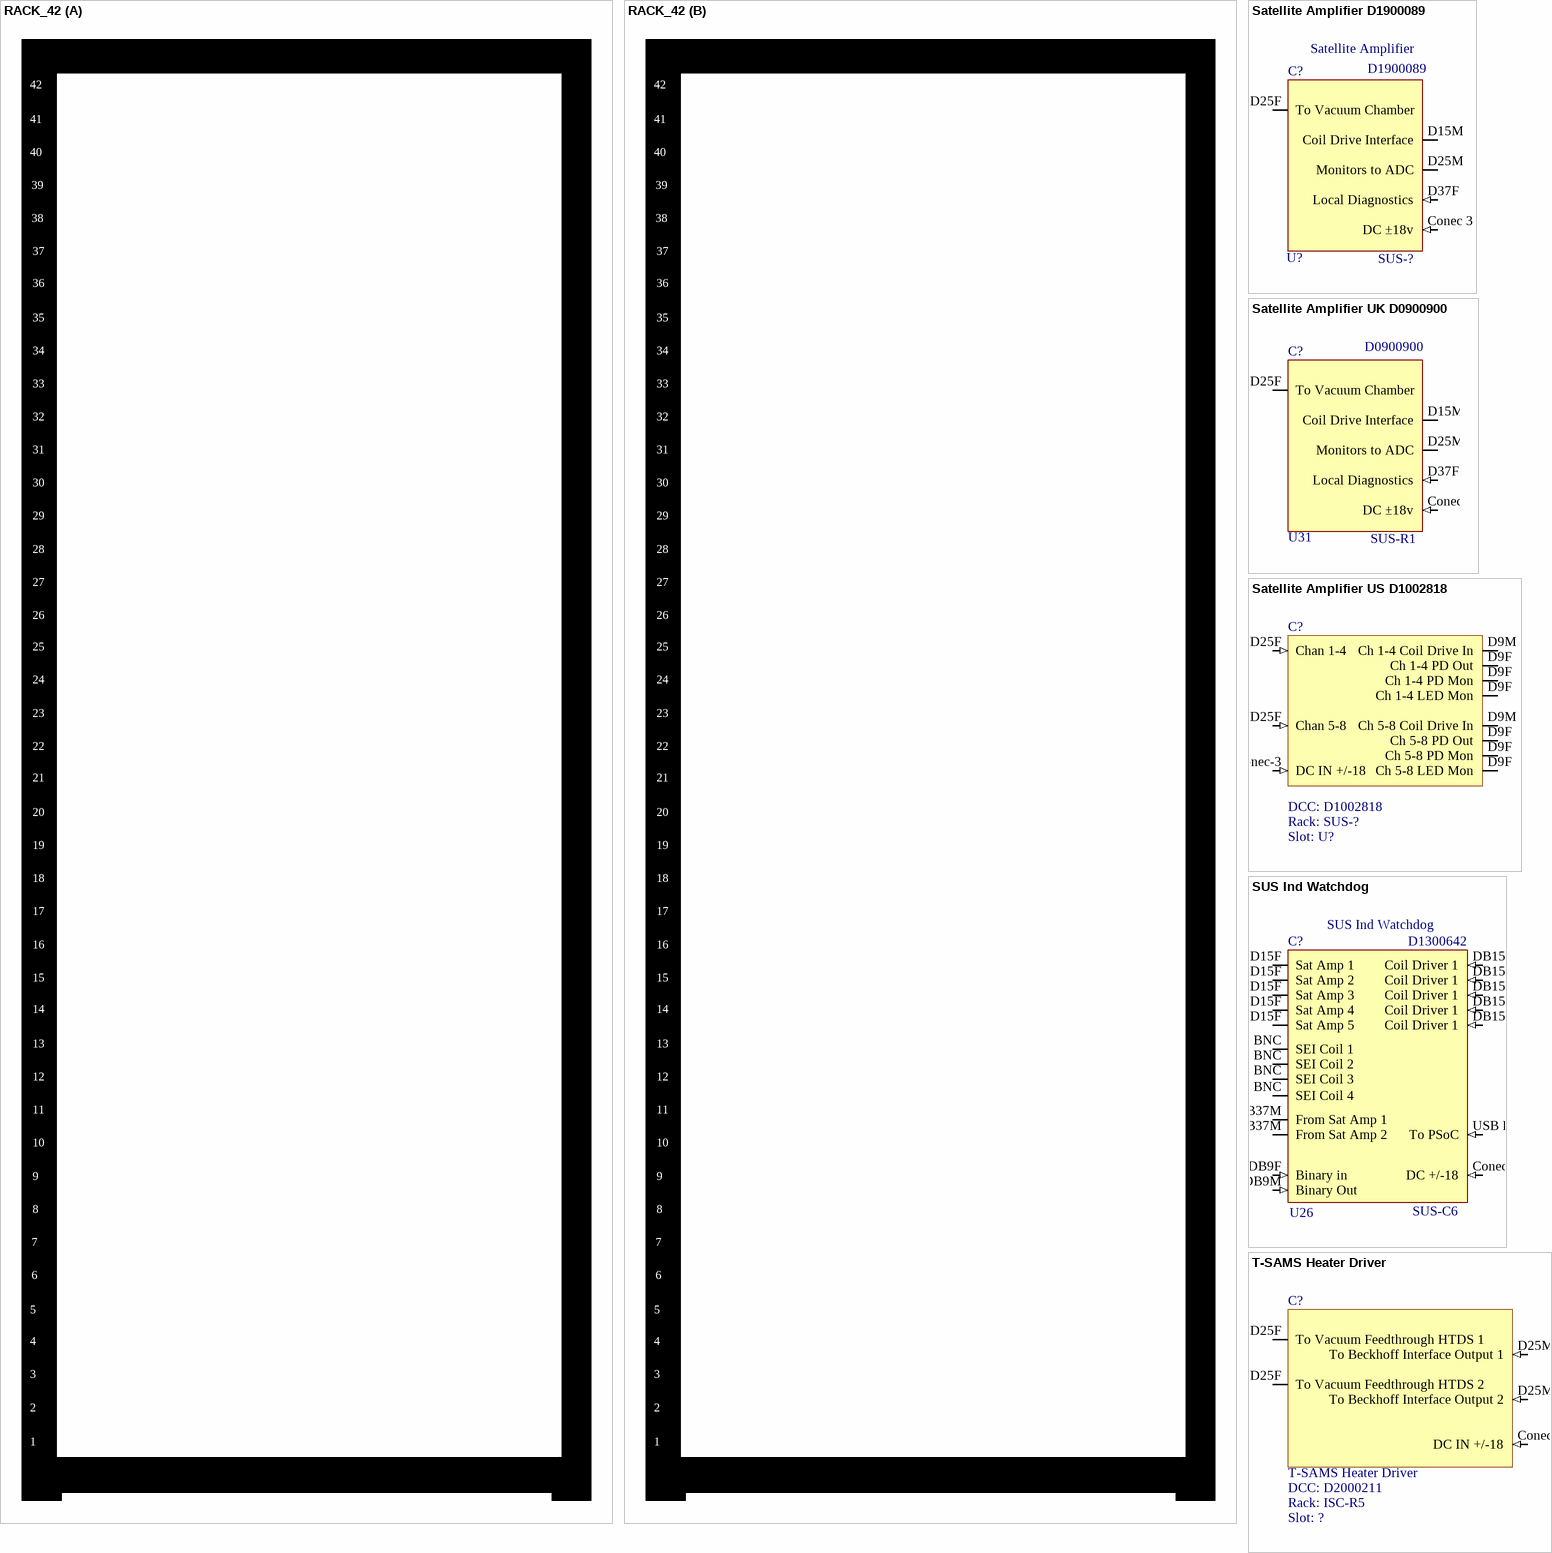
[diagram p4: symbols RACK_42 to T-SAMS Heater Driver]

## RACK_42
designator RackR?, comment 1U  Rack 42 pos  (value not drawn)

## Satellite Amplifier D1900089
designator C?, comment Satellite Amplifier  Slot: U?  Rack: SUS-?  DCC: D1900089
Serial: Sxxxxxxx
pins: Conec 3 DC ±18v (in), D15M Coil Drive Interface, D25F To Vacuum Chamber, D25M Monitors to ADC, D37F Local Diagnostics (in)

## Satellite Amplifier UK D0900900
designator C?  Slot: U31  Rack: SUS-R1  DCC: D0900900  (hidden comment: Satellite Amplifier UK D0900900)
System: SUS; Serial: Sxxxxxxx
pins: Conec 3 DC ±18v (in), D15M Coil Drive Interface, D25F To Vacuum Chamber, D25M Monitors to ADC, D37F Local Diagnostics (in)

## Satellite Amplifier US D1002818
designator C?, comment DCC: D1002818  Rack: SUS-?  Slot: U?  (hidden comment: Satellite Amplifier US D1002818 Dual)
Serial: Sxxxxxxx
pins: Conec-3 DC IN +/-18 (in), D9F Ch 1-4 PD Out, D9F Ch 1-4 PD Mon, D9F Ch 1-4 LED Mon, D9F Ch 5-8 PD Out, D9F Ch 5-8 PD Mon, D9F Ch 5-8 LED Mon, D9M Ch 1-4 Coil Drive In, D9M Ch 5-8 Coil Drive In, D25F Chan 1-4 (in), D25F Chan 5-8 (in)

## SUS Ind Watchdog
designator C?  Rack: SUS-C6  Slot: U26  DCC: D1300642
Serial: Sxxxxxxxx; Parameter: DB15 DB37 BNC
pins: BNC SEI Coil 1, BNC SEI Coil 2, BNC SEI Coil 3, BNC SEI Coil 4, Conec-3 DC +/-18 (in), D15F Sat Amp 1, D15F Sat Amp 2, D15F Sat Amp 3, D15F Sat Amp 4, D15F Sat Amp 5, DB9F Binary in (in), DB9M Binary Out (in), DB15M Coil Driver 1 (in), DB15M Coil Driver 1 (in), DB15M Coil Driver 1 (in), DB15M Coil Driver 1 (in), DB15M Coil Driver 1 (in), DB37M From Sat Amp 1, DB37M From Sat Amp 2, USB B-M To PSoC (in)

## T-SAMS Heater Driver
designator C?  DCC: D2000211  Rack: ISC-R5
Serial: Sxxxxxxx
pins: Conec-3 DC IN +/-18 (in), D25F To Vacuum Feedthrough HTDS 1, D25F To Vacuum Feedthrough HTDS 2, D25M To Beckhoff Interface Output 1 (in), D25M To Beckhoff Interface Output 2 (in)

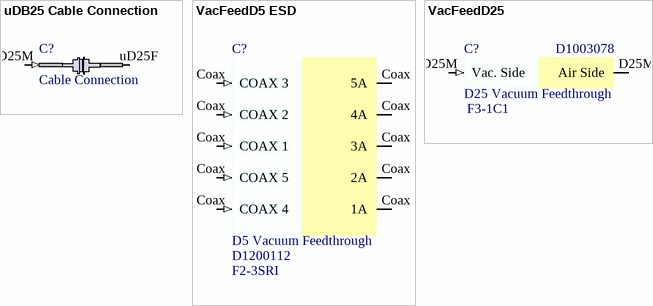
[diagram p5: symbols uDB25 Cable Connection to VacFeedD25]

## uDB25 Cable Connection
designator C?  value Cable Connection  (hidden comment: uDB25 Cable Connection)
Rack: SUS-R?; Serial: Sxxxxxxx; System: SUS
pins: uD25F, uD25M (in)

## VacFeedD5 ESD
designator C?, comment D5 Vacuum Feedthrough  DCC: D1200112  Chamber: F2-3SRI
Serial: Sxxxxxxx; System: ISC; Rack: R?; Slot: U?; Feedthrough: F2-3E1
pins: Coax 5A, Coax COAX 3 (in), Coax COAX 2 (in), Coax COAX 1 (in), Coax COAX 5 (in), Coax COAX 4 (in), Coax 4A, Coax 3A, Coax 2A, Coax 1A

## VacFeedD25
designator C?, comment D25 Vacuum Feedthrough  value F3-1C1  DCC: D1003078
Serial: Sxxxxxxx; System: ISC; Rack: R?; Slot: U?
pins: D25M Vac. Side (in), D25M Air Side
